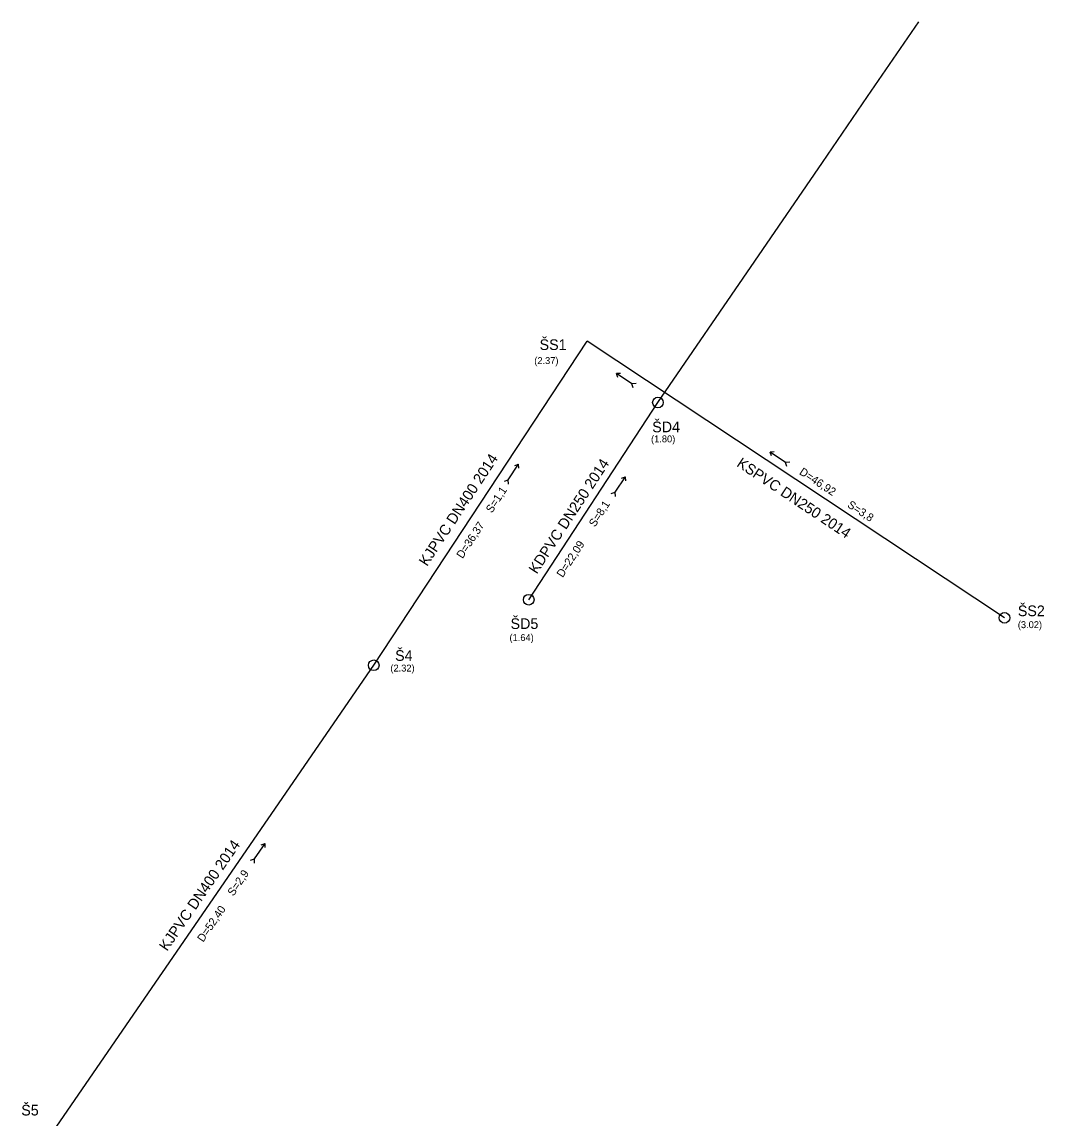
# Model space of a CAD drawing. Extents: x -539706 to -539225, y -1156458 to -1155912.
# Drawn here: x -539321.2 to -539225.4, y -1156100.8 to -1155998.1 of the extents above; entities that cross this region are included whole.
import ezdxf

# ---------------------------------------------------------------- set-up
doc = ezdxf.new("R2010")
doc.units = 0
for name, color, linetype in [('Vrstva 29', 7, 'Continuous'), ('Vrstva 39', 7, 'Continuous'), ('Vrstva 54', 7, 'Continuous'), ('Vrstva 56', 7, 'Continuous'), ('Vrstva 57', 7, 'Continuous'), ('Vrstva 7', 7, 'Continuous'), ('Vrstva 8', 7, 'Continuous')]:
    doc.layers.add(name, color=color, linetype=linetype)

msp = doc.modelspace()

# ---------------------------------------------------------------- linework, layer by layer
at = {"layer": 'Vrstva 29'}
for centre in [(-539261.61, -1156033.74), (-539273.72, -1156052.22), (-539229.14, -1156053.92), (-539288.24, -1156058.36)]:
    msp.add_circle(centre, 0.5, dxfattribs=at)
at = {"layer": 'Vrstva 39'}
for p, q in [((-539265.125, -1156031.007), (-539265.508, -1156031.029)), ((-539264.047, -1156032), (-539265.508, -1156031.029)), ((-539265.381, -1156031.393), (-539265.508, -1156031.029)), ((-539263.654, -1156031.974), (-539264.047, -1156032)), ((-539263.919, -1156032.371), (-539264.047, -1156032)), ((-539250.726, -1156038.357), (-539251.109, -1156038.379)), ((-539249.648, -1156039.35), (-539251.109, -1156038.379)), ((-539250.982, -1156038.743), (-539251.109, -1156038.379)), ((-539249.255, -1156039.324), (-539249.648, -1156039.35)), ((-539249.52, -1156039.721), (-539249.648, -1156039.35)), ((-539275.632, -1156040.986), (-539274.666, -1156039.522)), ((-539275.03, -1156039.65), (-539274.666, -1156039.522)), ((-539274.642, -1156039.905), (-539274.666, -1156039.522)), ((-539276.002, -1156041.116), (-539275.632, -1156040.986)), ((-539275.604, -1156041.379), (-539275.632, -1156040.986)), ((-539265.627, -1156042.147), (-539264.652, -1156040.689)), ((-539265.017, -1156040.814), (-539264.652, -1156040.689)), ((-539264.631, -1156041.072), (-539264.652, -1156040.689)), ((-539265.998, -1156042.274), (-539265.627, -1156042.147)), ((-539265.602, -1156042.54), (-539265.627, -1156042.147)), ((-539299.42, -1156076.507), (-539298.425, -1156075.062)), ((-539298.792, -1156075.183), (-539298.425, -1156075.062)), ((-539298.41, -1156075.445), (-539298.425, -1156075.062)), ((-539299.793, -1156076.629), (-539299.42, -1156076.507)), ((-539299.401, -1156076.9), (-539299.42, -1156076.507))]:
    msp.add_line(p, q, dxfattribs=at)
at = {"layer": 'Vrstva 8'}
for p, q in [((-539288.24, -1156058.36), (-539268.24, -1156027.98)), ((-539229.14, -1156053.92), (-539268.24, -1156027.98)), ((-539273.72, -1156052.22), (-539261.61, -1156033.74)), ((-539317.92, -1156101.55), (-539288.24, -1156058.36))]:
    msp.add_line(p, q, dxfattribs=at)
msp.add_lwpolyline([(-539261.61, -1156033.74), (-539252.53, -1156020.5), (-539246.18, -1156011.24), (-539241.96, -1156005.08), (-539237.16, -1155998.08)], dxfattribs=at)

# ---------------------------------------------------------------- texts
at = {"layer": 'Vrstva 54'}
for s, rotation, p in [('D=46,92', 326.43863, (-539248.431, -1156040.41)), ('S=1,1', 56.64195, (-539277.172, -1156044.153)), ('S=8,1', 56.76309, (-539267.515, -1156045.462)), ('S=3,8', 326.43864, (-539243.923, -1156043.492)), ('D=36,37', 56.64198, (-539279.924, -1156048.423)), ('D=22,09', 56.76305, (-539270.537, -1156050.199)), ('S=2,9', 55.50327, (-539301.39, -1156080.04)), ('D=52,40', 55.5033, (-539304.226, -1156084.359))]:
    msp.add_text(s, height=0.75, rotation=rotation, dxfattribs=at).set_placement(p)
at = {"layer": 'Vrstva 56'}
for s, p in [('(2.37)', (-539273.2, -1156030.14)), ('(1.80)', (-539262.257, -1156037.478)), ('(3.02)', (-539227.89, -1156054.88)), ('(1.64)', (-539275.52, -1156056.09)), ('(2.32)', (-539286.681, -1156058.949))]:
    msp.add_text(s, height=0.65, dxfattribs=at).set_placement(p)
at = {"layer": 'Vrstva 57'}
for s, p in [('ŠS1', (-539272.7, -1156028.82)), ('ŠD4', (-539262.147, -1156036.528)), ('ŠS2', (-539227.89, -1156053.76)), ('ŠD5', (-539275.42, -1156054.96)), ('Š4', (-539286.24, -1156057.947)), ('Š5', (-539321.267, -1156100.546))]:
    msp.add_text(s, height=1, dxfattribs=at).set_placement(p)
at = {"layer": 'Vrstva 7'}
for s, rotation, p in [('KJPVC DN400 2014', 56.64195, (-539283.246, -1156049.153)), ('KDPVC DN250 2014', 56.76309, (-539272.964, -1156049.878)), ('KSPVC DN250 2014', 326.43864, (-539254.309, -1156039.666)), ('KJPVC DN400 2014', 55.50327, (-539307.605, -1156085.213))]:
    msp.add_text(s, height=1, rotation=rotation, dxfattribs=at).set_placement(p)

doc.saveas('drawing.dxf')
